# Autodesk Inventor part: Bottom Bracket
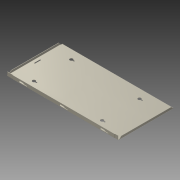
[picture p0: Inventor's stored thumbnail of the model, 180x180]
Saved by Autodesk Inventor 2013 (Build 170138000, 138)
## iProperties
Created: 2005-12
Material: Allgemein
Document SubType Name: Sheet Metal
Mass: 69.2391 g
Surface Area: 1400.33 cm^2
Volume: 69.2391 cm^3
Density: 1 g/cm^3
Flat Pattern Width: 18.8178 cm
Flat Pattern Length: 37.2355 cm
Flat Pattern Area: 700.69 cm^2
Sheet Metal Rule: 1.0 mm
Sheet Metal Width: 188.178 mm
Sheet Metal Length: 372.355 mm
Sheet Metal Area: 70068.975 mm^2
SPACING: 261.036 mm
Author: Autodesk, Inc.
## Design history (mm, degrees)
node "Face1"
  sketch "Sketch2"
    geometry: L1 (0, 89)-(359, 89); L2 (0, -89)-(0, 89); L3 (359, -89)-(0, -89); L4 (359, 89)-(359, -89)
    constraints: 8 end point
node "Flange1"
sketch "Sketch4"
  geometry: L1 (359, 0)-(0, 0) reference; L2 (0, -178)-(359, -178) reference; L3 (359, -4.99)-(356.922, -4.99); L4 (356.922, -4.99)-(356.922, 0); L5 (356.922, 0)-(359, 0); L6 (359, 0)-(359, -4.99); L7 (359, -168.01)-(357.5, -168.01); L8 (357.5, -168.01)-(357.5, -178); L9 (357.5, -178)-(359, -178); L10 (359, -178)-(359, -168.01); L11 (357.5, -168)-(357.5, -5) reference
  constraints: 16 end point, 4 parallel, 2 horizontal, 2 perpendicular, 2 point on line, 1 collinear
cut "Cut1" sketch "Sketch4" dims "d11" = 1 (= Thickness), "d12" = 0
node "Flange2"
node "Flange3"
cut "Cut4" dims "d70" = 1 (= Thickness), "d71" = 0
node "Flange4"
node "Flange6"
sketch "Sketch9"
  geometry: L1 (-357.5, -5.01)-(-357.5, -10) reference; L2 (-18, -8.49)-(0, -8.49); L3 (0, -8.49)-(0, -10); L4 (0, -10)-(-18, -10); L5 (-18, -10)-(-18, -8.49); L6 (-347.51, -10)-(-357.5, -10); L7 (-357.5, -10)-(-357.5, -8.5); L8 (-357.5, -8.5)-(-347.51, -8.5); L9 (-347.51, -8.5)-(-347.51, -10); L10 (-347.5, -8.5)-(-345.768, -8.5) reference
  constraints: 16 end point, 4 parallel, 2 horizontal, 2 perpendicular, 1 point on line
cut "Cut2" sketch "Sketch9" dims "d49" = 1 (= Thickness), "d50" = 0
feature "Corner Chamfer1" dims "d51" = 5, "d52" = 6, angle "d53" = 45 deg
sketch "Sketch10"
  geometry: L1 (20, 5.5)-(32, 5.5); L2 (32, 5.5)-(32, 1.5); L3 (32, 1.5)-(20, 1.5); L4 (20, 1.5)-(20, 5.5); L5 (32, 5.5)-(37, 3); L6 (37, 3)-(45, 3); L7 (45, 3)-(45, 1.5); L8 (45, 1.5)-(32, 1.5); L9 (-21.232, 6.5)-(-21.232, 1.5) reference; L10 (0, 10.5)-(0, 0) reference
  constraints: 16 end point, 4 perpendicular, 2 parallel, 1 horizontal
  dimensions: "d57" = 4 distance of L3.end L1.start; "d58" = 1.5 distance of L6.end L7.end; "d59" = 25 distance between parallel lines of L4 L7; "d60" = 8 distance of L5.end L6.end; "d62" = 12 distance of L1.start L1.end; "d68" = 20 distance between parallel lines of L10 L4
cut "Cut3" sketch "Sketch10" dims "d63" = 1 (= Thickness), "d64" = 0
pattern_linear "Rectangular Pattern1" dims "SPACING" = 261.0359 (computed from d54)
sketch "Sketch12"
  geometry: L1 (-37.4, 79)-(465.2, 79); L2 (8.5, 89)-(11.5, 89); L3 (11.5, 89)-(11.5, 69); L4 (11.5, 69)-(8.5, 69); L5 (8.5, 69)-(8.5, 89); L6 (-1.5, -10)-(-1.5, 168); L7 (357.5, 168)-(357.5, -10); L8 (58.5, 20.5)-(68.5, 20.5); L9 (68.5, 20.5)-(68.5, 17.5); L10 (68.5, 17.5)-(58.5, 17.5); L11 (58.5, 17.5)-(58.5, 20.5); L12 (58.5, 140.5)-(68.5, 140.5); L13 (68.5, 140.5)-(68.5, 137.5); L14 (68.5, 137.5)-(58.5, 137.5); L15 (58.5, 137.5)-(58.5, 140.5); L16 (277.5, 140.5)-(287.5, 140.5); L17 (287.5, 140.5)-(287.5, 137.5); L18 (287.5, 137.5)-(277.5, 137.5); L19 (277.5, 137.5)-(277.5, 140.5); L20 (277.5, 20.5)-(287.5, 20.5); L21 (287.5, 20.5)-(287.5, 17.5); L22 (287.5, 17.5)-(277.5, 17.5); L23 (277.5, 17.5)-(277.5, 20.5); C1 r 5 at (58.5, 19); C2 r 5 at (277.5, 19); C3 r 5 at (58.5, 139); C4 r 5 at (277.5, 139); 4 further points
  constraints: 46 end point, 10 parallel, 6 equal length, 5 horizontal, 5 perpendicular, 4 centre point, 4 coincident, 4 midpoint, 3 equal radius, 2 horizontal alignment, 2 vertical alignment, 1 symmetric about line, 1 other
  dimensions: "d72" = 3 distance of L2.start L2.end; "d73" = 20 distance of L2.end L3.end; "d74" = 10 distance between parallel lines of L6 L5; "d75" = 60 distance from line of C1.centre L6; "d76" = 80 distance from line of L7 C2.centre; "d77" = 120 distance of C1.centre C3.centre; "d78" = 10 diameter of C1; "d79" = 10 distance of L8.start L8.end; "d80" = 3 distance of L8.end L9.end
cut "Cut5" sketch "Sketch12" dims "d81" = 1 (= Thickness), "d82" = 0
body "Solid1"
face "Plate1" dims "Thickness" = 1
sketch "Sketch3"
  geometry: L1 (-5, 0)-(-168, 0); L2 (-168, 0)-(-168, 8); L3 (-168, 8)-(-5, 8); L4 (-5, 8)-(-5, 0)
  constraints: 8 end point
face "Plate2" dims "d2" = 10, "d3" = 5, "d6" = 2 (= MinimumRemnant), "d8" = 8, "d9" = 90 deg, "d10" = 0.5 (= BendRadius), "SeamGap" = 0.01, "Thickness" = 1
bend "Bend1" dims "d4" = 1 (= BendReliefWidth), "d5" = 0.5 (= BendReliefDepth), "d6" = 2 (= MinimumRemnant), "d7" = 0.5 (= BendRadius), "d8" = 8, "d9" = 90 deg, "d10" = 0.5 (= BendRadius), "SeamGap" = 0.01, "Thickness" = 1
sketch "Sketch5"
  geometry: L1 (-5, 0)-(-175, 0); L2 (-175, 0)-(-175, 8); L3 (-175, 8)-(-5, 8); L4 (-5, 8)-(-5, 0)
  constraints: 8 end point
face "Plate3" dims "d15" = 2 (= MinimumRemnant), "d17" = 8, "d18" = 90 deg, "d19" = 0.5 (= BendRadius), "d20" = 3, "d21" = 5, "SeamGap" = 0.01, "Thickness" = 1
bend "Bend2" dims "d13" = 1 (= BendReliefWidth), "d14" = 0.5 (= BendReliefDepth), "d15" = 2 (= MinimumRemnant), "d16" = 0.5 (= BendRadius), "d17" = 8, "d18" = 90 deg, "d19" = 0.5 (= BendRadius), "SeamGap" = 0.01, "Thickness" = 1
sketch "Sketch6"
  geometry: L1 (-18, 0)-(-347.5, 0); L2 (-347.5, 0)-(-347.5, 12); L3 (-347.5, 12)-(-18, 12); L4 (-18, 12)-(-18, 0)
  constraints: 8 end point
face "Plate4" dims "d22" = 10, "d23" = 18, "d26" = 2 (= MinimumRemnant), "d28" = 12, "d29" = 90 deg, "d30" = 0.5 (= BendRadius), "SeamGap" = 0.01, "Thickness" = 1
bend "Bend3" dims "d24" = 1 (= BendReliefWidth), "d25" = 0.5 (= BendReliefDepth), "d26" = 2 (= MinimumRemnant), "d27" = 0.5 (= BendRadius), "d28" = 12, "d29" = 90 deg, "d30" = 0.5 (= BendRadius), "SeamGap" = 0.01, "Thickness" = 1
sketch "Sketch7"
  geometry: L1 through (0, -5.25) direction (2.75e-15, -1); L2 (0, -10.5)-(17, -10.5); L3 (17, -10.5)-(17, 0); L4 through (8.5, 0) direction (-1, -2.35e-32)
  constraints: 6 end point, 1 horizontal, 1 perpendicular, 1 vertical
face "Plate5" dims "d33" = 2 (= MinimumRemnant), "d35" = 17, "d36" = 0, "d37" = 0.5 (= BendRadius), "SeamGap" = 0.01, "Thickness" = 1
bend "Bend4" dims "d31" = 1 (= BendReliefWidth), "d32" = 0.5 (= BendReliefDepth), "d33" = 2 (= MinimumRemnant), "d34" = 0.5 (= BendRadius), "d35" = 17, "d36" = 0, "d37" = 0.5 (= BendRadius), "SeamGap" = 0.01, "Thickness" = 1
sketch "Sketch11"
  geometry: L1 (-18, -8.49)-(0, -8.49); L2 (0, -8.49)-(0, -10); L3 (0, -10)-(-18, -10); L4 (-18, -10)-(-18, -8.49)
  constraints: 8 end point, 2 parallel, 1 horizontal, 1 perpendicular
sketch "Sketch13"
  geometry: L1 through (0, 5.25) direction (1.8e-31, -1); L2 through (-4.25, 0) direction (-1, -2.35e-32); L3 (-8.5, 0)-(-8.5, 10.5); L4 (-8.5, 10.5)-(0, 10.5)
  constraints: 6 end point, 1 horizontal, 1 perpendicular, 1 vertical
face "Plate7" dims "d83" = 1 (derived), "d84" = 0.5 (derived), "d85" = 2 (derived), "d86" = 0.5 (derived), "d87" = 8.5, "d88" = 0, "d89" = 0.5 (derived), "d90" = 4 (derived), "d91" = 1 (derived), "d92" = 1 (derived), "SeamGap" = 0.01, "Thickness" = 1
bend "Bend6" dims "d83" = 1 (derived), "d84" = 0.5 (derived), "d85" = 2 (derived), "d86" = 0.5 (derived), "d87" = 8.5, "d88" = 0, "d89" = 0.5 (derived), "SeamGap" = 0.01, "Thickness" = 1
feature "Corner1" dims "d87" = 8.5, "d88" = 0, "d90" = 4 (derived), "d91" = 1 (derived), "d92" = 1 (derived)
feature "Definition1"
other parameters: "BendRadius" = 0.5, "BendReliefWidth" = 1 (= Thickness), "BendReliefDepth" = 0.5 (= 0.5 x Thickness), "CornerReliefSize" = 4 (= 4 x Thickness), "MinimumRemnant" = 2 (= 2 x Thickness), "TransitionRadius" = 0.5 (= BendRadius), "d1" = 0.5 (= BendRadius), "d54" = 326.0359 (derived), "JacobiRadiusSize" = 1 (derived), "GapSize" = 1 (derived), "BendRadius" = 0.5, "BendReliefDepth" = 0.5, "BendReliefWidth" = 1, "CornerReliefSize" = 4, "JacobiRadiusSize" = 1, "MinimumRemnant" = 2, "SPACING" = 261.0359, "Thickness" = 1, "TransitionRadius" = 0.5, "GapSize" = 1
